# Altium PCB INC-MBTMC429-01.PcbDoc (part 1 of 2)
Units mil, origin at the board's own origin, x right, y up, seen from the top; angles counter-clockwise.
Board outline 6000 x 4000 mil, 2 copper layers (Top Layer, Bottom Layer); 198 components, 197 nets, 672 pads, 128 vias.
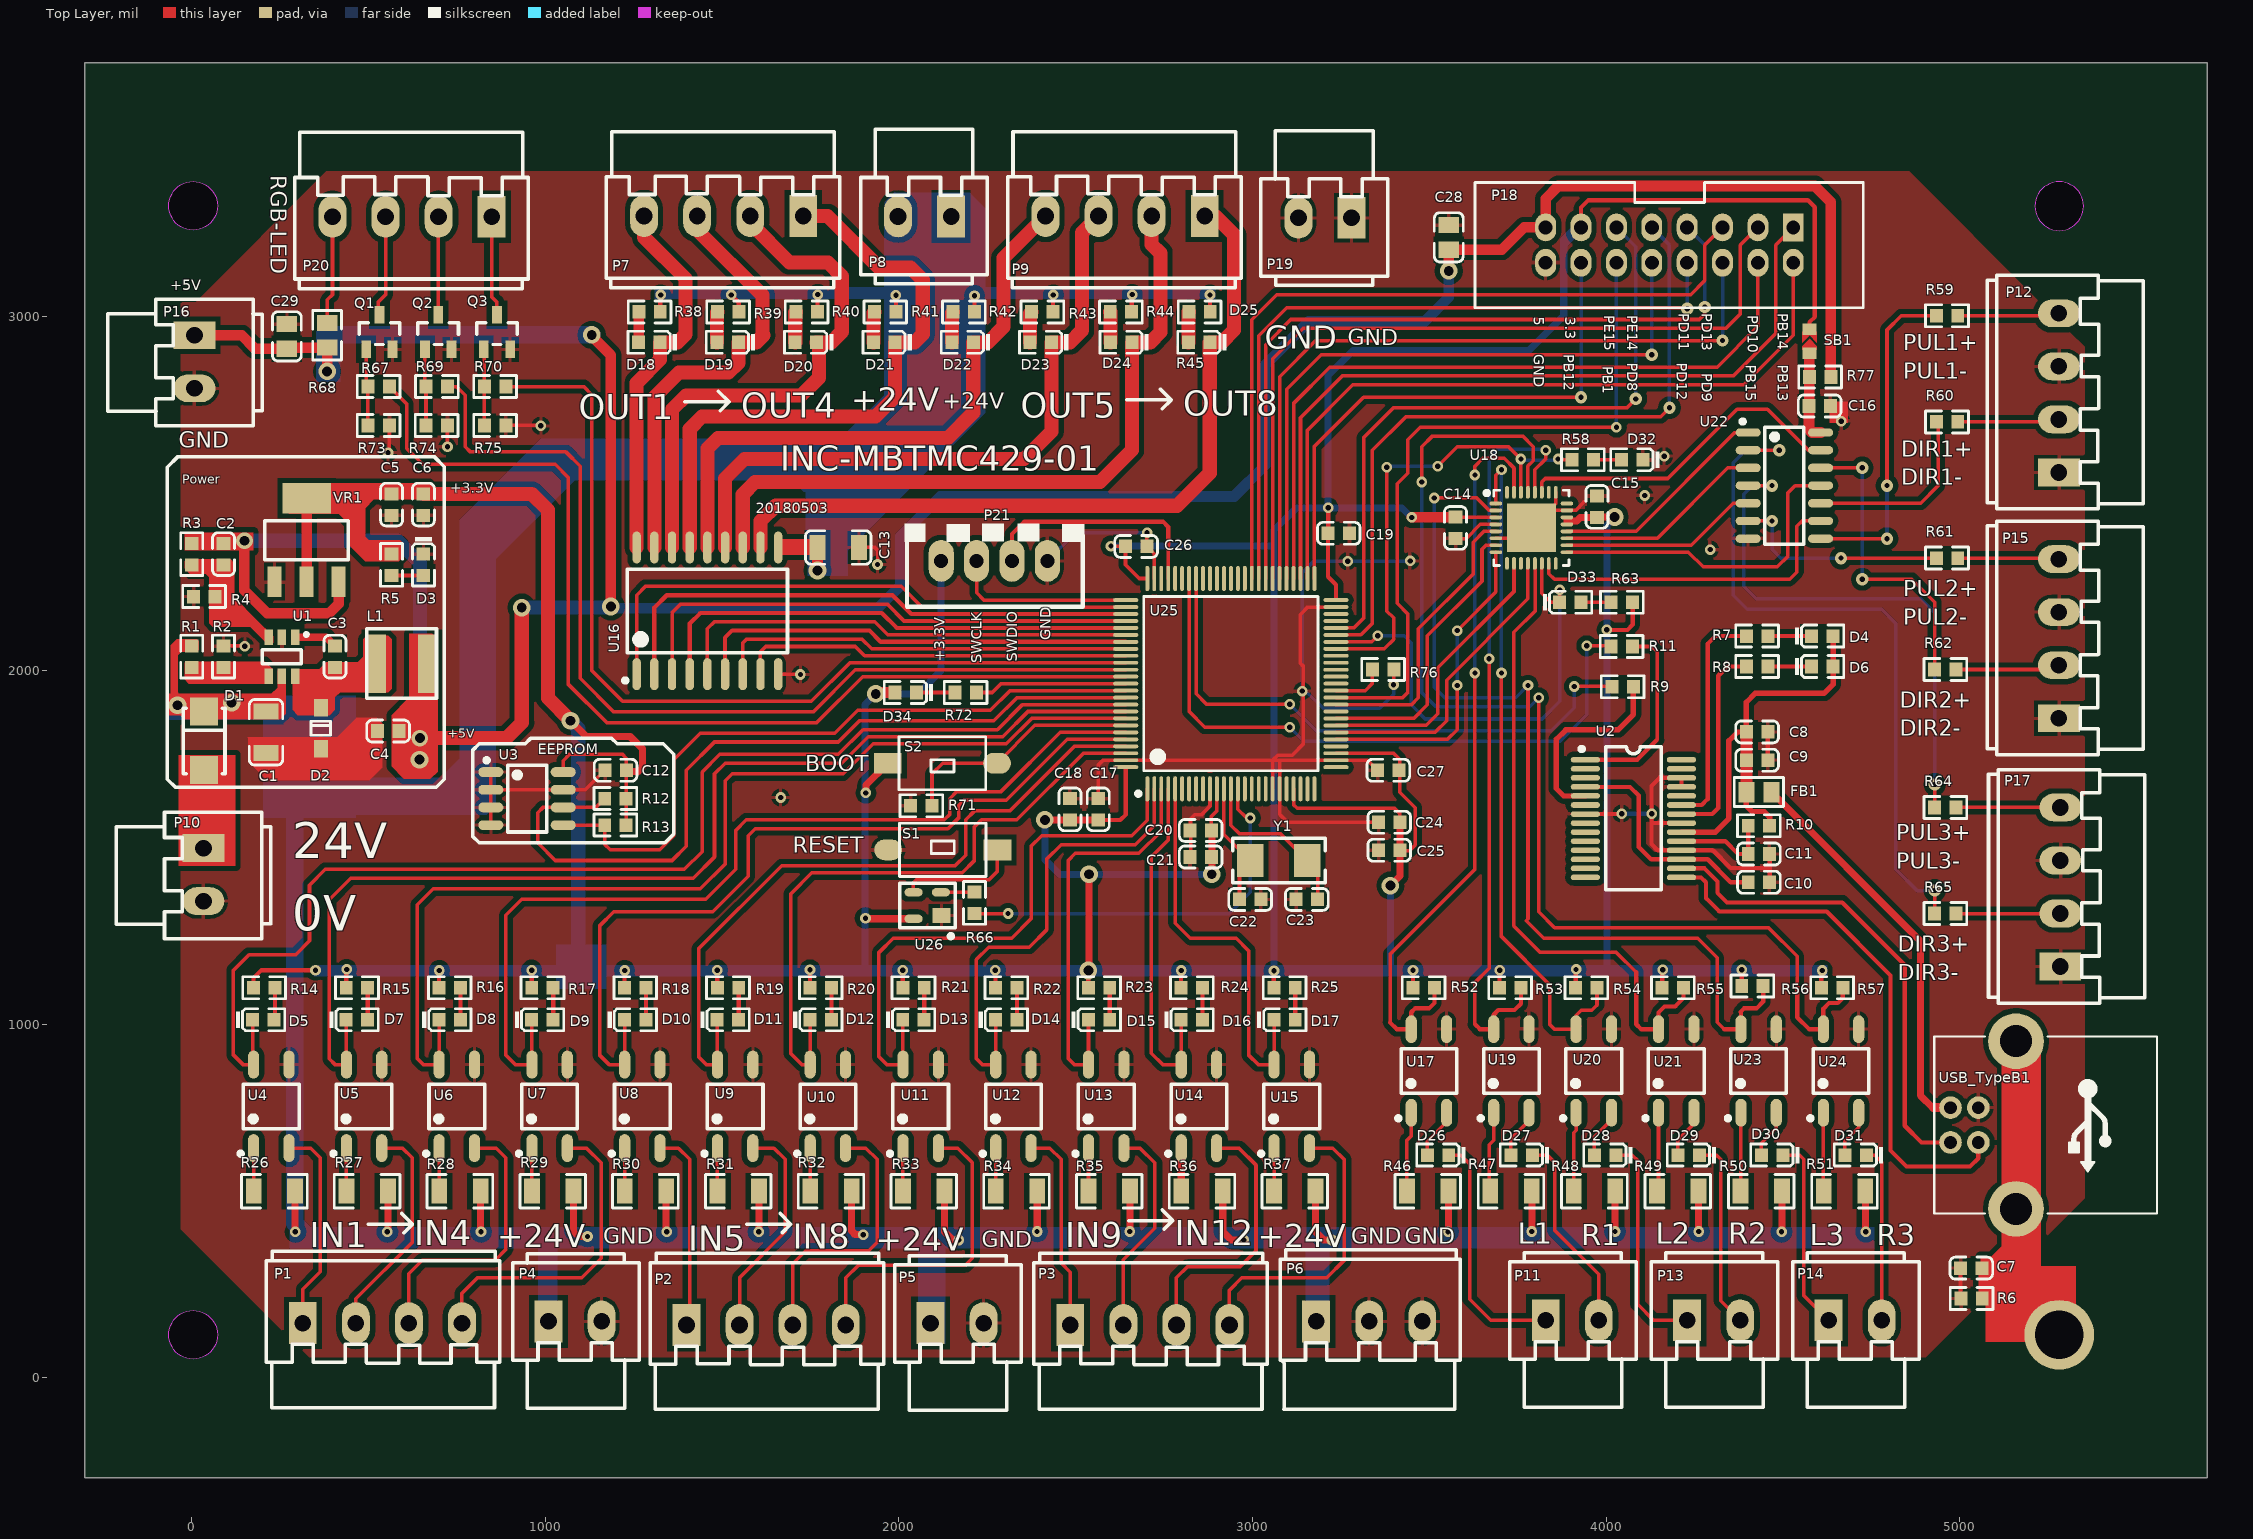
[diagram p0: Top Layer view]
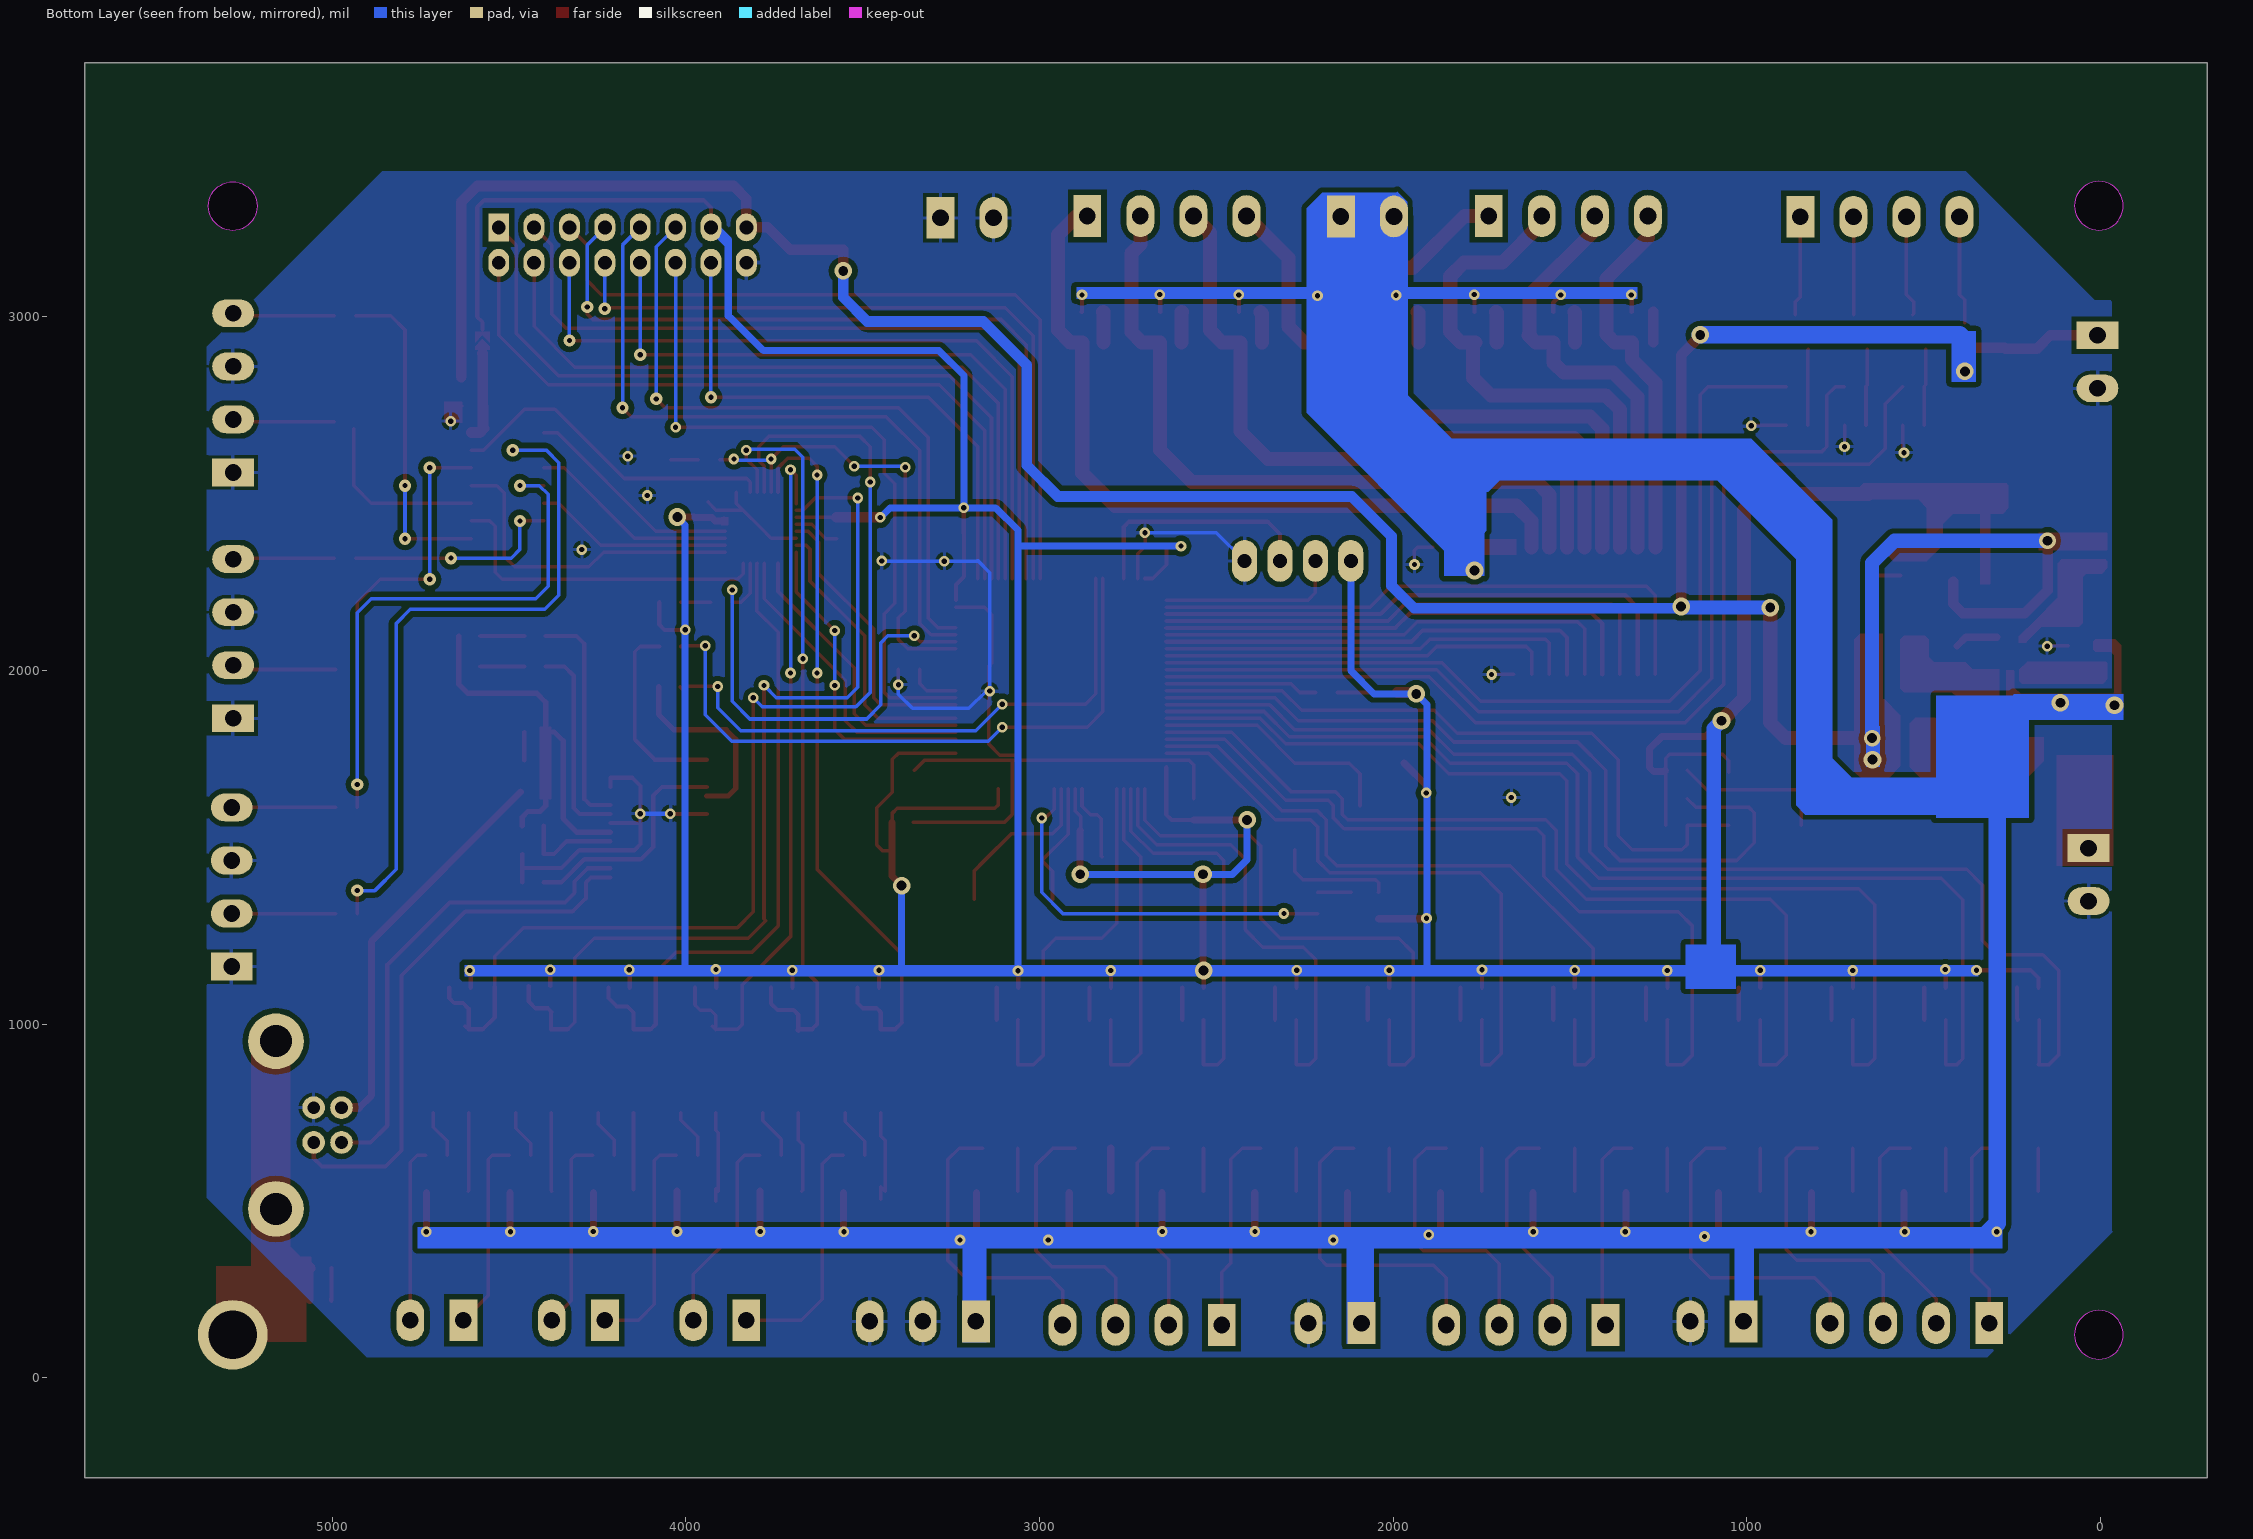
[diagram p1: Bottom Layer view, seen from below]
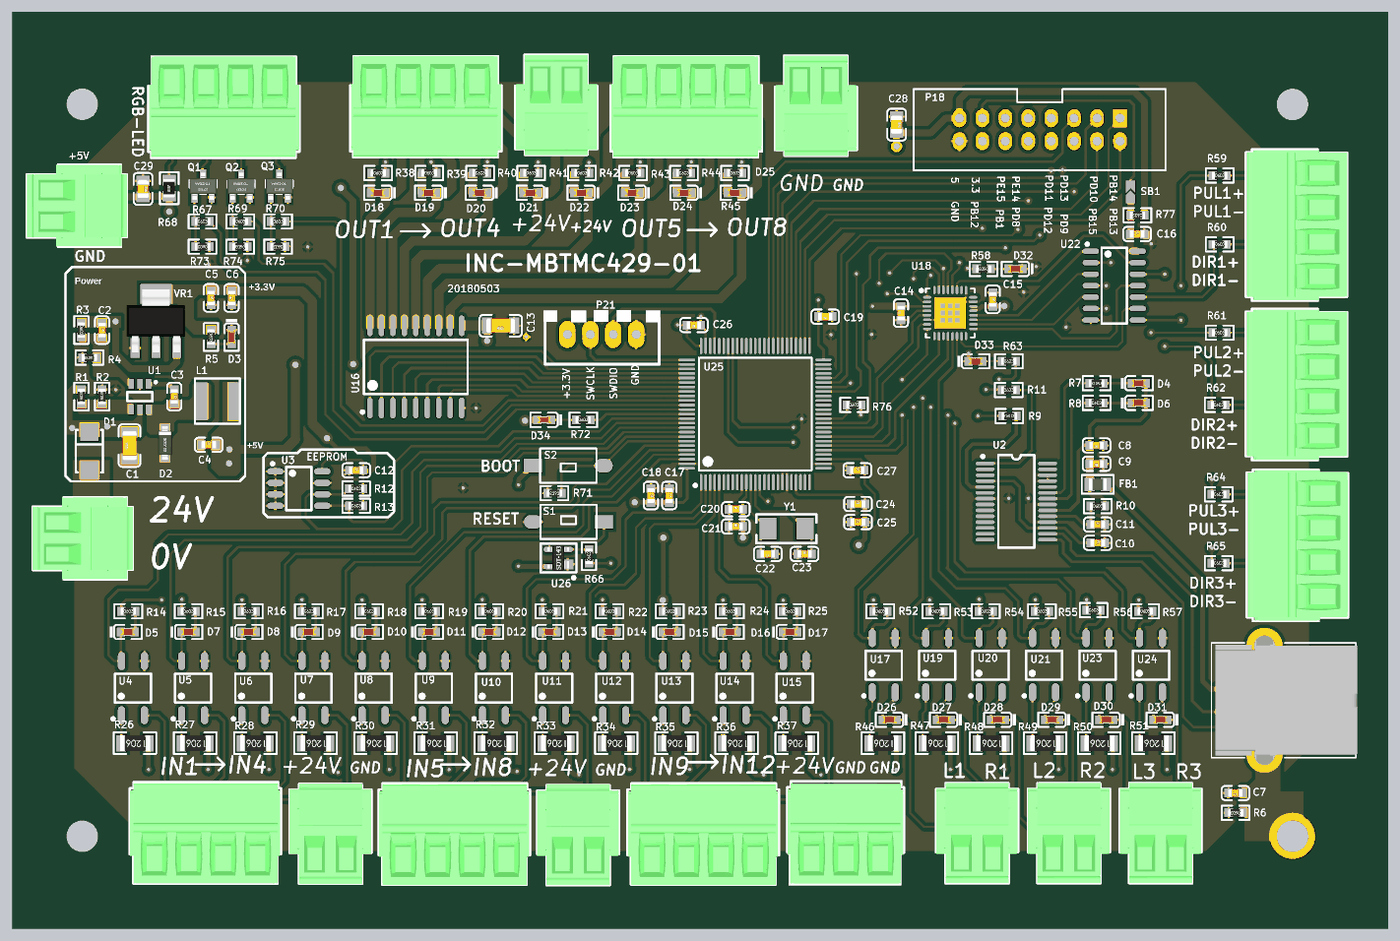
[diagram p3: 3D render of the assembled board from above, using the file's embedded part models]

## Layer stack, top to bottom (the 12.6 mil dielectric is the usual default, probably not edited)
Top Solder: solder mask 0.4, Solder Resist, Dk 3.5
Top Layer: signal copper 1.4
Dielectric 1: dielectric 12.6, FR-4, Dk 4.8
Bottom Layer: signal copper 1.4
Bottom Solder: solder mask 0.4, Solder Resist, Dk 3.5

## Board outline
-301,-282 5699,-282 5699,3718 -301,3718
cut-out: 5212.1,3313 ccw(c5281,3313) 5281,3244.1 ccw(c5281,3313) 5349.9,3313 ccw(c5281,3313) 5281,3381.9 ccw(c5281,3313)
cut-out: 5,3245.1 cw(c5,3314) -63.9,3314 cw(c5,3314) 5,3382.9 cw(c5,3314) 73.9,3314 cw(c5,3314)
cut-out: 5,53.1 cw(c5,122) -63.9,122 cw(c5,122) 5,190.9 cw(c5,122) 73.9,122 cw(c5,122)

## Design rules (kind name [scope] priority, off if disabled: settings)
Clearance [All] p1: gap=8 ignorepadtopadclearanceinfootprint=FALSE
MinimumSolderMaskSliver [All] p1 off: minsoldermaskwidth=10
PolygonConnect [All] p1: connectstyle=Relief reliefconductorwidth=10 reliefentries=4 polygonreliefangle="90 Angle" airgapwidth=10
RoutingVias [All] p1: holewidth=28 width=50 viastyle="Through Hole" minholewidth=15 minwidth=30 maxholewidth=28 maxwidth=50
SilkToSilkClearance [All] p1 off: silktosilkclearance=10
SilkToSolderMaskClearance [IsPad] p1 off: minsilkscreentomaskgap=10 clearancetoexposedcopper=TRUE
SolderMaskExpansion [All] p1: expansion=4
Width [All] p1: maxlimit=100 minlimit=10 preferedwidth=10
27 further rules are at their usual default settings.

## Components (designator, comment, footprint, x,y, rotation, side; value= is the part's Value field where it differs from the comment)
C1 "10uF (106) 10% 50V" 1206_C 211,1825.34 r90 top
C2 "33pF (330) 5% 50V" 0603_C 91,2329.32 r270 top
C3 "100nF (104) 10% 50V" 0603_C 406,2039.32 r270 top
C4 "10uF (106) 10% 10V" 0603_C 556.32,1829 r0 top
C5 "10uF (106) 10% 10V" 0603_C 566,2469.32 r270 top
C6 "100nF (104) 10% 50V" 0603_C 656,2469.32 r90 top
C7 "100nF (104) 10% 50V" 0603_C 5032.31,310.53 r180 top
C8 "10uF (106) 10% 10V" 0603_C 4426.69,1826.5 r180 top
C9 "100nF (104) 10% 50V" 0603_C 4426.69,1746.5 r180 top
C10 "100nF (104) 10% 50V" 0603_C 4432,1401.5 r0 top
C11 "100nF (104) 10% 50V" 0603_C 4432,1481.5 r0 top
C12 "100nF (104) 10% 50V" 0603_C 1199.32,1718 r0 top
C13 "10uF(106) ±10% 25V" 1206_C 1829,2348 r180 top
C14 "100nF (104) 10% 50V" 0603_C 3574,2403.32 r90 top
C15 "470nF (474) 10% 25V" 0603_C 3974,2463 r270 top
C16 "100nF (104) 10% 50V" 0603_C 4603.69,2748 r0 top
C17 "100nF (104) 10% 50V" 0603_C 2564,1607.68 r270 top
C18 "4.7uF (475) 10% 16V" 0603_C 2484,1607.68 r270 top
C19 "100nF (104) 10% 50V" 0603_C 3244,2388 r180 top
C20 "1uF (105) 10% 50V" 0603_C 2853.69,1548 r0 top
C21 "10nF (103) 10% 50V" 0603_C 2853.69,1473 r0 top
C22 "22pF (220) 5% 50V" 0603_C 2993.69,1353 r180 top
C23 "22pF (220) 5% 50V" 0603_C 3153.69,1353 r0 top
C24 "1uF (105) 10% 50V" 0603_C 3386.69,1571 r0 top
C25 "10nF (103) 10% 50V" 0603_C 3386.69,1492 r0 top
C26 "100nF (104) 10% 50V" 0603_C 2671.32,2351 r180 top
C27 "100nF (104) 10% 50V" 0603_C 3384,1718 r0 top
C28 "10uF (106) 10% 25V" 0805_C 3555,3224.96 r270 top
C29 "10uF (106) 10% 25V" 0805_C 270,2945.04 r270 top
D1 "SS210" SMA(DO-214AC)_S1 36,1801.32 r270 top
D2 "B5819W  SL" SOD-123 366,1837.07 r270 top
D3 "红灯 0603" 0603_LED_S1 656,2299.32 r270 top
D4 "蓝灯 0603" 0603_LED_S1 4611.31,2097.5 r0 top
D5 "蓝灯 0603" 0603_LED_S1 203.68,1013 r0 top
D6 "红灯 0603" 0603_LED_S1 4611.31,2011.5 r0 top
D7 "蓝灯 0603" 0603_LED_S1 467.96,1013 r0 top
D8 "蓝灯 0603" 0603_LED_S1 730.23,1013 r0 top
D9 "蓝灯 0603" 0603_LED_S1 992.5,1013 r0 top
D10 "蓝灯 0603" 0603_LED_S1 1254.78,1013 r0 top
D11 "蓝灯 0603" 0603_LED_S1 1517.05,1013 r0 top
D12 "蓝灯 0603" 0603_LED_S1 1779.32,1013 r0 top
D13 "蓝灯 0603" 0603_LED_S1 2041.59,1013 r0 top
D14 "蓝灯 0603" 0603_LED_S1 2303.87,1013 r0 top
D15 "蓝灯 0603" 0603_LED_S1 2566.14,1013 r0 top
D16 "蓝灯 0603" 0603_LED_S1 2828.41,1013 r0 top
D17 "蓝灯 0603" 0603_LED_S1 3090.68,1013 r0 top
D18 "蓝灯 0603" 0603_LED_S1 1294.69,2928 r180 top
D19 "蓝灯 0603" 0603_LED_S1 1516.11,2928 r180 top
D20 "蓝灯 0603" 0603_LED_S1 1737.54,2928 r180 top
D21 "蓝灯 0603" 0603_LED_S1 1958.97,2928 r180 top
D22 "蓝灯 0603" 0603_LED_S1 2180.4,2928 r180 top
D23 "蓝灯 0603" 0603_LED_S1 2401.83,2928 r180 top
D24 "蓝灯 0603" 0603_LED_S1 2629,2928 r180 top
D25 "蓝灯 0603" 0603_LED_S1 2849,2928 r180 top
D26 "红灯 0603" 0603_LED_S1 3524.69,630 r180 top
D27 "红灯 0603" 0603_LED_S1 3760.81,630 r180 top
D28 "红灯 0603" 0603_LED_S1 3996.94,630 r180 top
D29 "红灯 0603" 0603_LED_S1 4233.06,630 r180 top
D30 "红灯 0603" 0603_LED_S1 4469.19,630 r180 top
D31 "红灯 0603" 0603_LED_S1 4705.32,630 r180 top
D32 "蓝灯 0603" 0603_LED_S1 4073.32,2596 r180 top
D33 "红灯 0603" 0603_LED_S1 3899,2193 r0 top
D34 "蓝灯 0603" 0603_LED_S1 2019.32,1938 r180 top
FB1 "600Ω ±25% 100MHz" 0805_L 4432,1656.5 r0 top
L1 "3.3uH  ±20%" L5020 596,2019 r0 top value="4.7uH  ±10%"
P1 "Header 4" WJ15EDGVC-3.81-4P 315,155 r0 top
P2 "Header 4" WJ15EDGVC-3.81-4P 1400,150 r0 top
P3 "Header 4" WJ15EDGVC-3.81-4P 2485,150 r0 top
P4 "Header 2" WJ15EDGVC-3.81-2P 1010,160 r0 top
P5 "Header 2" WJ15EDGVC-3.81-2P 2090,155 r0 top
P6 "Header 3" WJ15EDGVC-3.81-3P 3180,160 r0 top
P7 "Header 4" WJ15EDGVC-3.81-4P 1730,3285 r180 top
P8 "Header 2" WJ15EDGVC-3.81-2P 2148,3284 r180 top
P9 "Header 4" WJ15EDGVC-3.81-4P 2865,3285 r180 top
P10 "Header 2" WJ15EDGVC-3.81-2P 34,1498 r270 top
P11 "Header 2" WJ15EDGVC-3.81-2P 3829,163 r0 top
P12 "Header 4" WJ15EDGVC-3.81-4P 5280,2560 r90 top
P13 "Header 2" WJ15EDGVC-3.81-2P 4229,163 r0 top
P14 "Header 2" WJ15EDGVC-3.81-2P 4629,163 r0 top
P15 "Header 4" WJ15EDGVC-3.81-4P 5280,1865 r90 top
P16 "Header 2" WJ15EDGVC-3.81-2P 9,2948 r270 top
P17 "Header 4" WJ15EDGVC-3.81-4P 5284,1163 r90 top
P18 "Header 8X2H" "直牛角连接器 2*8*2.54" 4529,3253 r180 top
P19 "Header 2" WJ15EDGVC-3.81-2P 3280,3280 r180 top
P20 "Header 4" WJ15EDGVC-3.81-4P 849,3283 r180 top
P21 "SWD" "XH连接器 4P-2.5" 2120,2310 r180 top
Q1 "SS8050 Y1" SOT-23(SOT-23-3) 531.6,2957.21 r270 top
Q2 "SS8050 Y1" SOT-23(SOT-23-3) 697.8,2957.21 r270 top
Q3 "SS8050 Y1" SOT-23(SOT-23-3) 864,2957.21 r270 top
R1 "47KΩ (4702) ±1%" 0603_R 1,2039.31 r90 top
R2 "10KΩ (1002) ±1%" 0603_R 91,2039.31 r90 top
R3 "160KΩ (1603) ±1%" 0603_R 1,2329.32 r270 top
R4 "30KΩ (3002) ±1%" 0603_R 36.32,2209 r180 top
R5 "1KΩ (1001) ±1%" 0603_R 566,2299 r270 top
R6 "47KΩ (4702) ±1%" 0603_R 5033,224.53 r180 top
R7 "1KΩ (1001) ±1%" 0603_R 4426.69,2097.5 r180 top
R8 "1KΩ (1001) ±1%" 0603_R 4426.68,2011.5 r0 top
R9 "33Ω (33R0) ±1%" 0603_R 4046.68,1954.5 r0 top
R10 "10KΩ (1002) ±1%" 0603_R 4432,1561.5 r0 top
R11 "33Ω (33R0) ±1%" 0603_R 4044,2068 r0 top
R12 "4.7KΩ (4701) ±1%" 0603_R 1199,1638 r0 top
R13 "4.7KΩ (4701) ±1%" 0603_R 1199,1563 r0 top
R14 "1KΩ (1001) ±1%" 0603_R 206,1103 r0 top
R15 "1KΩ (1001) ±1%" 0603_R 468.24,1103 r0 top
R16 "1KΩ (1001) ±1%" 0603_R 730.49,1103 r0 top
R17 "1KΩ (1001) ±1%" 0603_R 992.73,1103 r0 top
R18 "1KΩ (1001) ±1%" 0603_R 1254.98,1103 r0 top
R19 "1KΩ (1001) ±1%" 0603_R 1517.22,1103 r0 top
R20 "1KΩ (1001) ±1%" 0603_R 1779.46,1103 r0 top
R21 "1KΩ (1001) ±1%" 0603_R 2041.71,1103 r0 top
R22 "1KΩ (1001) ±1%" 0603_R 2303.95,1103 r0 top
R23 "1KΩ (1001) ±1%" 0603_R 2566.2,1103 r0 top
R24 "1KΩ (1001) ±1%" 0603_R 2828.44,1103 r0 top
R25 "1KΩ (1001) ±1%" 0603_R 3090.68,1103 r0 top
R26 "4.7KΩ (4701) ±1%" 1206_R 234.66,528 r180 top
R27 "4.7KΩ (4701) ±1%" 1206_R 496.93,528 r180 top
R28 "4.7KΩ (4701) ±1%" 1206_R 759.21,528 r180 top
R29 "4.7KΩ (4701) ±1%" 1206_R 1021.48,528 r180 top
R30 "4.7KΩ (4701) ±1%" 1206_R 1283.75,528 r180 top
R31 "4.7KΩ (4701) ±1%" 1206_R 1546.02,528 r180 top
R32 "4.7KΩ (4701) ±1%" 1206_R 1808.3,528 r180 top
R33 "4.7KΩ (4701) ±1%" 1206_R 2070.57,528 r180 top
R34 "4.7KΩ (4701) ±1%" 1206_R 2332.84,528 r180 top
R35 "4.7KΩ (4701) ±1%" 1206_R 2595.12,528 r180 top
R36 "4.7KΩ (4701) ±1%" 1206_R 2857.39,528 r180 top
R37 "4.7KΩ (4701) ±1%" 1206_R 3119.66,528 r180 top
R38 "6.8KΩ (6801) ±1%" 0603_R 1295.31,3014 r0 top
R39 "6.8KΩ (6801) ±1%" 0603_R 1517.46,3014 r0 top
R40 "6.8KΩ (6801) ±1%" 0603_R 1739.6,3014 r0 top
R41 "6.8KΩ (6801) ±1%" 0603_R 1961.74,3014 r0 top
R42 "6.8KΩ (6801) ±1%" 0603_R 2183.89,3014 r0 top
R43 "6.8KΩ (6801) ±1%" 0603_R 2406.03,3014 r0 top
R44 "6.8KΩ (6801) ±1%" 0603_R 2628.17,3014 r0 top
R45 "6.8KΩ (6801) ±1%" 0603_R 2850.31,3014 r0 top
R46 "4.7KΩ (4701) ±1%" 1206_R 3495.38,528 r180 top
R47 "4.7KΩ (4701) ±1%" 1206_R 3731.11,528 r180 top
R48 "4.7KΩ (4701) ±1%" 1206_R 3966.83,528 r180 top
R49 "4.7KΩ (4701) ±1%" 1206_R 4202.55,528 r180 top
R50 "4.7KΩ (4701) ±1%" 1206_R 4438.28,528 r180 top
R51 "4.7KΩ (4701) ±1%" 1206_R 4674,528 r180 top
R52 "1KΩ (1001) ±1%" 0603_R 3484,1103 r0 top
R53 "1KΩ (1001) ±1%" 0603_R 3728.68,1103 r0 top
R54 "1KΩ (1001) ±1%" 0603_R 3944,1103 r0 top
R55 "1KΩ (1001) ±1%" 0603_R 4188.68,1103 r0 top
R56 "1KΩ (1001) ±1%" 0603_R 4413.68,1108 r0 top
R57 "1KΩ (1001) ±1%" 0603_R 4638.68,1103 r0 top
R58 "1KΩ (1001) ±1%" 0603_R 3934.32,2596 r180 top
R59 "220Ω (2200) ±1%" 0603_R 4963.68,3003 r0 top
R60 "220Ω (2200) ±1%" 0603_R 4963.68,2703 r0 top
R61 "220Ω (2200) ±1%" 0603_R 4963.68,2318 r0 top
R62 "220Ω (2200) ±1%" 0603_R 4959,2003 r0 top
R63 "1KΩ (1001) ±1%" 0603_R 4044.31,2193 r0 top
R64 "220Ω (2200) ±1%" 0603_R 4959,1613 r0 top
R65 "220Ω (2200) ±1%" 0603_R 4959,1313 r0 top
R66 "4.7KΩ (4701) ±1%" 0603_R 2214,1343 r90 top
R67 "2.2KΩ (2201) ±1%" 0603_R 529.31,2803 r0 top
R68 "1KΩ (1001) ±1%" 0805_R 384,2948.04 r90 top
R69 "2.2KΩ (2201) ±1%" 0603_R 694.16,2803 r0 top
R70 "2.2KΩ (2201) ±1%" 0603_R 859,2803 r0 top
R71 "100KΩ (1003) ±1%" 0603_R 2063.69,1618 r180 top
R72 "510Ω (5100) ±1%" 0603_R 2189,1938 r0 top
R73 "100KΩ (1003) ±1%" 0603_R 529.32,2693 r180 top
R74 "100KΩ (1003) ±1%" 0603_R 693.69,2693 r180 top
R75 "100KΩ (1003) ±1%" 0603_R 858.69,2693 r180 top
R76 "100KΩ (1003) ±1%" 0603_R 3369.31,2003 r0 top
R77 "0Ω (0R0) ±1%" 0603_R 4605,2830 r180 top
S1 "贴片按键 3*6*2.5" "贴片按键 3*6*2.5" 2279,1493 r180 top
S2 "贴片按键 3*6*2.5" "贴片按键 3*6*2.5" 1969,1738 r0 top
SB1 "Circuit Breaker" JP2_SMD 4575,2897.5 r90 top
U1 "MP2451DT-LF-Z" SOT-23-6 256,2039 r90 top
U2 "FT232RL-REEL" SSOP-28_208mil 4077,1581.5 r270 top
U3 "EEPROM/AT24C128" SOIC-8_150mil 949,1638 r270 top
U4 "EL357N(B)(TA)-G" SOP-4_P2.54 226,768 r90 top
U5 "EL357N(B)(TA)-G" SOP-4_P2.54 488.27,768 r90 top
U6 "EL357N(B)(TA)-G" SOP-4_P2.54 750.55,768 r90 top
U7 "EL357N(B)(TA)-G" SOP-4_P2.54 1012.82,768 r90 top
U8 "EL357N(B)(TA)-G" SOP-4_P2.54 1275.09,768 r90 top
U9 "EL357N(B)(TA)-G" SOP-4_P2.54 1537.36,768 r90 top
U10 "EL357N(B)(TA)-G" SOP-4_P2.54 1799.64,768 r90 top
U11 "EL357N(B)(TA)-G" SOP-4_P2.54 2061.91,768 r90 top
U12 "EL357N(B)(TA)-G" SOP-4_P2.54 2324.18,768 r90 top
U13 "EL357N(B)(TA)-G" SOP-4_P2.54 2586.45,768 r90 top
U14 "EL357N(B)(TA)-G" SOP-4_P2.54 2848.73,768 r90 top
U15 "EL357N(B)(TA)-G" SOP-4_P2.54 3111,768 r90 top
U16 "ULN2803ADW" SOIC-18_300mil 1459,2168.87 r0 top
U17 "EL357N(B)(TA)-G" SOP-4_P2.54 3499,868 r90 top
U18 "TMC429-LI" QFN-32_5x5x05P 3788.61,2403.47 r270 top
U19 "EL357N(B)(TA)-G" SOP-4_P2.54 3732,868 r90 top
U20 "EL357N(B)(TA)-G" SOP-4_P2.54 3965,868 r90 top
U21 "EL357N(B)(TA)-G" SOP-4_P2.54 4198,868 r90 top
U22 "74HC04D" SOIC-14_150mil 4504,2523 r270 top
U23 "EL357N(B)(TA)-G" SOP-4_P2.54 4431,868 r90 top
U24 "EL357N(B)(TA)-G" SOP-4_P2.54 4664,868 r90 top
U25 "STM32F103VET6" LQFP-100_14x14x05P 2939,1963 r0 top
U26 "IMP811" SOT-143 2081.2,1335.6 r0 top
USB_TypeB1 "USB-B" USB_TypeB 5012.72,715.01 r270 top
VR1 "AMS1117-3.3" SOT-223 326,2369 r270 top
Y1 "8MHz ±20ppm 20pF" SMD-5032_2P 3074.71,1463 r180 top

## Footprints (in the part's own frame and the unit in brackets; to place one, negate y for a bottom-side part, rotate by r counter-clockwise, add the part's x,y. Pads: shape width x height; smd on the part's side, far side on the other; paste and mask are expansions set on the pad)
0603_C [mm]
  rect 0.93x0.98 smd: 1(-0.77,0) 2(0.77,0)
  silkscreen extent -1.53,-0.79 1.54,0.79, body extent -0.8,-0.4 0.8,0.4, height 0.3
0603_LED_S1 [mm]
  rect 0.93x0.98 smd: A(0.77,0) K(-0.77,0)
  silkscreen extent -1.98,-0.79 1.54,0.79, body extent -0.8,-0.4 0.8,0.4, height 0.6
0603_R [mm]
  rect 0.93x0.98 smd: 1(-0.77,0) 2(0.77,0)
  silkscreen extent -1.53,-0.79 1.54,0.79, body extent -0.85,-0.4 0.85,0.4, height 0.56
0805_C [mm]
  rect 1.16x1.47 smd: 1(-0.89,0) 2(0.89,0)
  silkscreen extent -1.77,-1.04 1.77,1.04, body extent -1,-0.62 1,0.63, height 0.77
0805_L [mm]
  rect 1.16x1.47 smd: 1(-0.89,0) 2(0.89,0)
  silkscreen extent -1.77,-1.04 1.77,1.03, body extent -1.02,-0.64 1.03,0.64, height 0.6
0805_R [mm]
  rect 1.16x1.47 smd: 1(-0.89,0) 2(0.89,0)
  silkscreen extent -1.77,-1.04 1.77,1.03, body extent -1,-0.62 1,0.63, height 0.49
1206_C [mm]
  rect 1.13x1.8 smd: 1(-1.49,0) 2(1.49,0)
  silkscreen extent -2.36,-1.2 2.35,1.2, body extent -1.6,-0.81 1.6,0.79, height 1
1206_R [mm]
  rect 1.13x1.8 smd: 1(-1.49,0) 2(1.49,0)
  silkscreen extent -2.36,-1.2 2.35,1.2, body extent -1.7,-0.86 1.65,0.87, height 0.85
JP2_SMD [mil] "短路焊点"
  rect 32x40 smd: 1(0,0) 2(67.5,0)
  Top Layer region: 60,0 50,0 30,20 60,20
  Top Layer region: 60,0 50,0 30,-20 60,-20
  Top Layer region: 10,-20 20,-20 40,0 20,20 10,20
L5020 [mm] "XCP 功率电感 5*5*2"
  rect 1.4x4.2 smd: 1(-1.85,0) 2(1.85,0)
  silkscreen extent -2.54,-2.49 2.46,2.51
LQFP-100_14x14x05P [mm]
  oval 0.28x1.8 smd mask+0.051: 1(-6,-7.55) 2(-5.5,-7.55) 3(-5,-7.55) 4(-4.5,-7.55) 5(-4,-7.55) 6(-3.5,-7.55) 7(-3,-7.55) 8(-2.5,-7.55) 9(-2,-7.55) 10(-1.5,-7.55) 11(-1,-7.55) 12(-0.5,-7.55) 13(0,-7.55) 14(0.5,-7.55) 15(1,-7.55) 16(1.5,-7.55) 17(2,-7.55) 18(2.5,-7.55) 19(3,-7.55) 20(3.5,-7.55) 21(4,-7.55) 22(4.5,-7.55) 23(5,-7.55) 24(5.5,-7.55) 25(6,-7.55) 51(6,7.55) 52(5.5,7.55) 53(5,7.55) 54(4.5,7.55) 55(4,7.55) 56(3.5,7.55) 57(3,7.55) 58(2.5,7.55) 59(2,7.55) 60(1.5,7.55) 61(1,7.55) 62(0.5,7.55) 63(0,7.55) 64(-0.5,7.55) 65(-1,7.55) 66(-1.5,7.55) 67(-2,7.55) 68(-2.5,7.55) 69(-3,7.55) 70(-3.5,7.55) 71(-4,7.55) 72(-4.5,7.55) 73(-5,7.55) 74(-5.5,7.55) 75(-6,7.55)
  oval 1.8x0.28 smd mask+0.051: 26(7.55,-6) 27(7.55,-5.5) 28(7.55,-5) 29(7.55,-4.5) 30(7.55,-4) 31(7.55,-3.5) 32(7.55,-3) 33(7.55,-2.5) 34(7.55,-2) 35(7.55,-1.5) 36(7.55,-1) 37(7.55,-0.5) 38(7.55,0) 39(7.55,0.5) 40(7.55,1) 41(7.55,1.5) 42(7.55,2) 43(7.55,2.5) 44(7.55,3) 45(7.55,3.5) 46(7.55,4) 47(7.55,4.5) 48(7.55,5) 49(7.55,5.5) 50(7.55,6) 76(-7.55,6) 77(-7.55,5.5) 78(-7.55,5) 79(-7.55,4.5) 80(-7.55,4) 81(-7.55,3.5) 82(-7.55,3) 83(-7.55,2.5) 84(-7.55,2) 85(-7.55,1.5) 86(-7.55,1) 87(-7.55,0.5) 88(-7.55,0) 89(-7.55,-0.5) 90(-7.55,-1) 91(-7.55,-1.5) 92(-7.55,-2) 93(-7.55,-2.5) 94(-7.55,-3) 95(-7.55,-3.5) 96(-7.55,-4) 97(-7.55,-4.5) 98(-7.55,-5) 99(-7.55,-5.5) 100(-7.55,-6)
  silkscreen extent -6.8,-8.05 6.25,6.25
QFN-32_5x5x05P [mm]
  rect 3.5x3.5 smd paste-1.75 mask+0.051: 0(0,0)
  oval 0.28x0.9 smd mask+0.051: 1(-1.75,-2.55) 2(-1.25,-2.55) 3(-0.75,-2.55) 4(-0.25,-2.55) 5(0.25,-2.55) 6(0.75,-2.55) 7(1.25,-2.55) 8(1.75,-2.55) 17(1.75,2.55) 18(1.25,2.55) 19(0.75,2.55) 20(0.25,2.55) 21(-0.25,2.55) 22(-0.75,2.55) 23(-1.25,2.55) 24(-1.75,2.55)
  oval 0.9x0.28 smd mask+0.051: 9(2.55,-1.75) 10(2.55,-1.25) 11(2.55,-0.75) 12(2.55,-0.25) 13(2.55,0.25) 14(2.55,0.75) 15(2.55,1.25) 16(2.55,1.75) 25(-2.55,1.75) 26(-2.55,1.25) 27(-2.55,0.75) 28(-2.55,0.25) 29(-2.55,-0.25) 30(-2.55,-0.75) 31(-2.55,-1.25) 32(-2.55,-1.75)
  silkscreen extent -2.7,-3.35 2.7,2.7
SMA(DO-214AC)_S1 [mm]
  rect 2x2 smd: 1(2.1,0) 2(-2.1,0)
  silkscreen extent -2.35,-1.5 2.35,1.5
SMD-5032_2P [mm]
  rect 1.9x2.4 smd: 1(-2.05,0) 2(2.05,0)
  silkscreen extent -3.32,-1.6 3.32,1.6
SOD-123 [mm]
  rect 1.25x1 smd: 1(1.475,0) 2(-1.475,0)
  silkscreen extent -0.5,-0.7 0.5,0.7, body extent -1.85,-0.77 1.85,0.78, height 1.35
SOIC-8_150mil [mm]
  oval 0.7x1.8 smd: 1(-1.905,-2.6) 2(-0.635,-2.6) 3(0.635,-2.6) 4(1.905,-2.6) 5(1.905,2.6) 6(0.635,2.6) 7(-0.635,2.6) 8(-1.905,2.6)
  silkscreen extent -2.9,-3.05 2.4,1.4
SOIC-14_150mil [mm]
  oval 0.6x1.8 smd: 1(-3.81,-2.6) 2(-2.54,-2.6) 3(-1.27,-2.6) 4(0,-2.6) 5(1.27,-2.6) 6(2.54,-2.6) 7(3.81,-2.6) 8(3.81,2.6) 9(2.54,2.6) 10(1.27,2.6) 11(0,2.6) 12(-1.27,2.6) 13(-2.54,2.6) 14(-3.81,2.6)
  silkscreen extent -4.75,-3.15 4.2,1.4
SOIC-18_300mil [mm]
  oval 0.6x2.3 smd: 1(-5.08,-4.55) 2(-3.81,-4.55) 3(-2.54,-4.55) 4(-1.27,-4.55) 5(0,-4.55) 6(1.27,-4.55) 7(2.54,-4.55) 8(3.81,-4.55) 9(5.08,-4.55) 10(5.08,4.55) 11(3.81,4.55) 12(2.54,4.55) 13(1.27,4.55) 14(0,4.55) 15(-1.27,4.55) 16(-2.54,4.55) 17(-3.81,4.55) 18(-5.08,4.55)
  silkscreen extent -6.05,-5.15 5.75,3
SOP-4_P2.54 [mm]
  oval 2x0.8 smd: 1(-3,1.27) 2(-3,-1.27) 3(3,-1.27) 4(3,1.27)
  silkscreen extent -3.55,-2 1.6,2.35
SOT-23(SOT-23-3) [mm]
  rect 1.25x0.7 smd: 1(1.25,-0.95) 2(1.25,0.95) 3(-1.25,0)
  silkscreen extent -0.65,-1.46 0.9,1.46, body extent -1.5,-1.5 1.5,1.5, height 1.3
SOT-23-6 [mm]
  rect 1.1x0.6 smd: 1(1.4,-0.95) 2(1.4,0) 3(1.4,0.95) 4(-1.4,0.95) 5(-1.4,0) 6(-1.4,-0.95)
  silkscreen extent -0.5,-1.87 1.72,1.4
SOT-143 [mm]
  rect 1.3x1.1 smd: 1(1,-0.71)
  oval 1.3x0.6 smd: 2(0.96,0.95) 3(-1,0.95) 4(-1,-0.95)
  silkscreen extent -1.98,-2.35 1.98,1.6, body extent -1.23,-1.46 1.19,1.46, height 1
SOT-223 [mm]
  rect 2.2x1 smd: 1(3,-2.3) 2(3,0) 3(3,2.3)
  rect 2.2x3.5 smd: 2(-3,0)
  silkscreen extent -1.4,-3 1.4,3, body extent -3.49,-3.24 3.49,3.24, height 1.64
SSOP-28_208mil [mm]
  oval 0.4x2.1 smd mask+0.051: 1(-4.225,-3.45) 2(-3.575,-3.45) 3(-2.925,-3.45) 4(-2.275,-3.45) 5(-1.625,-3.45) 6(-0.975,-3.45) 7(-0.325,-3.45) 8(0.325,-3.45) 9(0.975,-3.45) 10(1.625,-3.45) 11(2.275,-3.45) 12(2.925,-3.45) 13(3.575,-3.45) 14(4.225,-3.45) 15(4.225,3.45) 16(3.575,3.45) 17(2.925,3.45) 18(2.275,3.45) 19(1.625,3.45) 20(0.975,3.45) 21(0.325,3.45) 22(-0.325,3.45) 23(-0.975,3.45) 24(-1.625,3.45) 25(-2.275,3.45) 26(-2.925,3.45) 27(-3.575,3.45) 28(-4.225,3.45)
  silkscreen extent -5.15,-3.86 5.1,2
USB_TypeB [mil]
  round 64 hole 36 mask+1: 1(-49.21,-39.16) 2(49.21,-39.16) 3(49.21,39.58) 4(-49.21,39.58)
  round 157.48 hole 90.55 mask+0: 5(-237.01,146.28) 6(237.01,146.28)
  silkscreen extent -250,-85 250,545, body extent -283,-67 283,551, height 453
WJ15EDGVC-3.81-2P [mm] "XCP 15EDG连接器 直 插件 P=3.81"
  rect 2x3 hole 1.2: 1(0,0)
  oval 2x3 hole 1.2: 2(3.81,0)
  silkscreen extent -2.59,-6.25 6.5,4.85, body extent -2.57,-6.22 6.44,4.88, height 18.95
WJ15EDGVC-3.81-3P [mm] "XCP 15EDG连接器 直 插件 P=3.81"
  rect 2x3 hole 1.2: 1(0,0)
  oval 2x3 hole 1.2: 2(3.81,0) 3(7.62,0)
  silkscreen extent -2.59,-6.3 10.34,5.13, body extent -2.56,-6.2 10.26,4.9, height 18.6
WJ15EDGVC-3.81-4P [mm] "XCP 15EDG连接器 直 插件 P=3.81"
  rect 2x3 hole 1.2: 1(0,0)
  oval 2x3 hole 1.2: 2(3.81,0) 3(7.62,0) 4(11.43,0)
  silkscreen extent -2.62,-6.07 14.15,5.16, body extent -2.57,-6.07 14.06,5.03, height 18.6
"XH连接器 4P-2.5" [mil] "XCP"
  oval 71x118 hole 39.37: 1(0,0) 2(-100,0) 3(-200,0) 4(-300,0)
  silkscreen extent -405,-106 103,130
"直牛角连接器 2*8*2.54" [mm] "XCP"
  rect 1.5x2 hole 1: 1(0,0)
  oval 1.5x2 hole 1: 2(0,2.54) 3(2.54,0) 4(2.54,2.54) 5(5.08,0) 6(5.08,2.54) 7(7.62,0) 8(7.62,2.54) 9(10.16,0) 10(10.16,2.54) 11(12.7,0) 12(12.7,2.54) 13(15.24,0) 14(15.24,2.54) 15(17.78,0) 16(17.78,2.54)
  silkscreen extent -5.03,-3.23 22.86,5.77
"贴片按键 3*6*2.5" [mm] "XCP"
  rect 2x1.5 smd: 1(0,0)
  oval 2x1.5 smd: 2(7.849,0)
  silkscreen extent 0.81,-1.91 7.04,1.91

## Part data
C1: library part "1206 10uF (106) 10% 50V", "贴片电容", Package=1206, SuppliersPartNumber=C13585
C2: library part "0603 33pF (330) 5% 50V", "贴片电容", Package=0603, SuppliersPartNumber=C1663
C3 C6 C7 C9 C10 C11 C12 C14 C16 C17 C19 C26 C27: library part "0603 100nF (104) 10% 50V", "贴片电容", Package=0603, SuppliersPartNumber=C14663
C4 C5 C8: library part "0603 10uF (106) 10% 10V", "贴片电容", Package=0603, SuppliersPartNumber=C19702
C13: library part Cap, "Capacitor"
C15: library part "0603 470nF (474) 10% 25V", "贴片电容", Package=0603, SuppliersPartNumber=C1623
C18: library part "0603 4.7uF (475) 10% 16V", "贴片电容", Package=0603, SuppliersPartNumber=C19666
C20 C24: library part "0603 1uF (105) 10% 50V", "贴片电容", Package=0603, SuppliersPartNumber=C15849
C21 C25: library part "0603 10nF (103) 10% 50V", "贴片电容", Package=0603, SuppliersPartNumber=C57112
C22 C23: library part "0603 22pF (220) 5% 50V", "贴片电容", Package=0603, SuppliersPartNumber=C1653
C28 C29: library part "0805 10uF (106) 10% 25V", "贴片电容", Package=0805, SuppliersPartNumber=C15850
D1: library part "SMA(DO-214AC) SS210", "二极管", Package=SMA(DO-214AC), SuppliersPartNumber=C14996
D2: library part "SOD-123 B5819W  SL", "肖特基二极管", Package=SOD-123, SuppliersPartNumber=C8598
D3 D6 D26 D27 D28 D29 D30 D31 D33: library part "0603 红灯", "发光二极管", Package=0603, SuppliersPartNumber=C2286
D4 D5 D7 D8 D9 D10 D11 D12 D13 D14 D15 D16 D17 D18 D19 D20 D21 D22 D23 D24 D25 D32 D34: library part "0603 蓝灯", "发光二极管", Package=0603, SuppliersPartNumber=C72041
FB1: library part "0805 600Ω 25% 100MHz", "贴片磁珠", Package=0805, SuppliersPartNumber=C1017
L1: library part Inductor, "Inductor"
P1 P2 P3 P7 P9 P12 P15 P17 P20: "Header, 4-Pin"
P4 P5 P8 P10 P11 P13 P14 P16 P19: "Header, 2-Pin"
P6: "Header, 3-Pin"
P18: "Header, 8-Pin, Dual row, Right Angle"
P21: library part MHDR1X4, "Header, 4-Pin"
Q1 Q2 Q3: library part "SOT-23 SS8050 Y1", "三极管", Package=SOT-23, SuppliersPartNumber=C2150
R1 R6: library part "0603 47KΩ (4702) 1%", "贴片电阻", Package=0603, SuppliersPartNumber=C25819
R2 R10 R12 R13: library part "0603 10KΩ (1002) 1%", "贴片电阻", Package=0603, SuppliersPartNumber=C25804
R3: library part "0603 130KΩ (1303) 1%", "贴片电阻", Package=0603, SuppliersPartNumber=C22795
R4: library part "0603 24KΩ (2402) 1%", "贴片电阻", Package=0603, SuppliersPartNumber=C23352
R5 R7 R8 R14 R15 R16 R17 R18 R19 R20 R21 R22 R23 R24 R25 R52 R53 R54 R55 R56 R57 R58 R63: library part "0603 1KΩ (1001) 1%", "贴片电阻", Package=0603, SuppliersPartNumber=C21190
R9 R11: library part "0603 330Ω (3300) 1%", "贴片电阻", Package=0603, SuppliersPartNumber=C23138
R26 R27 R28 R29 R30 R31 R32 R33 R34 R35 R36 R37 R46 R47 R48 R49 R50 R51: library part "1206 4.7KΩ (4701) 1%", "贴片电阻", Package=1206, SuppliersPartNumber=C17936
R38 R39 R40 R41 R42 R43 R44 R45: library part "0603 6.8KΩ (6801) 1%", "贴片电阻", Package=0603, SuppliersPartNumber=C23212
R59 R60 R61 R62 R64 R65: library part "0603 220Ω (2200) 1%", "贴片电阻", Package=0603, SuppliersPartNumber=C22962
R66: library part "0603 4.7KΩ (4701) 1%", "贴片电阻", Package=0603, SuppliersPartNumber=C23162
R67 R69 R70: library part "0603 2.2KΩ (2201) 1%", "贴片电阻", Package=0603, SuppliersPartNumber=C4190
R68: library part "0805 2KΩ (2001) 1%", "贴片电阻", Package=0805, SuppliersPartNumber=C17604
R71 R73 R74 R75 R76: library part "0603 100KΩ (1003) 1%", "贴片电阻", Package=0603, SuppliersPartNumber=C25803
R72: library part "0603 510Ω (5100) 1%", "贴片电阻", Package=0603, SuppliersPartNumber=C23193
R77: library part "0603 0Ω (0R0) 1%", "贴片电阻", Package=0603, SuppliersPartNumber=C21189
S1 S2: library part SW-PB, "Switch"
U1: "DC-DCоƬ", Package=SOT-23-6, SuppliersPartNumber=C14123
U2: library part FT232RL
U3: library part EEPROM/AT24C256C-SSHL-T_[C6482], "EEPROM", Package=SOIC-8_150mil, SuppliersPartNumber=C6482
U4 U5 U6 U7 U8 U9 U10 U11 U12 U13 U14 U15 U17 U19 U20 U21 U23 U24: "贴片光耦", Package=SOP-4_P2.54, SuppliersPartNumber=C6649
U16: "大电流驱动", Package=SOIC-18_300mil, SuppliersPartNumber=C9683
U22: library part 74HC04
USB_TypeB1: library part USB-6
VR1: library part "SOT-223 AMS1117-3.3", "低压差线性稳压(LDO)", Package=SOT-223, SuppliersPartNumber=C6186
Y1: library part "SMD-5032_2P 8MHz 20ppm 20pF", "贴片晶振", Package=SMD-5032_2P, SuppliersPartNumber=C115962

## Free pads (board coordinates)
  round 196.85 hole 137.8: 0(5281,122)

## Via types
v1: diameter 30, hole 15, Top Layer to Bottom Layer, tented both sides, 91 vias
v2: diameter 35, hole 15, Top Layer to Bottom Layer, tented both sides, 17 vias
v3: diameter 50, hole 28, Top Layer to Bottom Layer, tented both sides, 16 vias
v4: diameter 47.24, hole 28, Top Layer to Bottom Layer, tented both sides, 2 vias
v5: diameter 30, hole 15, Top Layer to Bottom Layer, 1 vias
v6: diameter 50, hole 28, Top Layer to Bottom Layer, 1 vias

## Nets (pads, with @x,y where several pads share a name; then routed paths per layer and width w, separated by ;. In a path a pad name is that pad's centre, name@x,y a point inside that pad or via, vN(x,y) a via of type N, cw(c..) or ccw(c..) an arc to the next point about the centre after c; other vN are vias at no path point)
+3.3V: C5.1 C6.2 C12.2 C14.2 C15.2 C17.2 C18.2 C19.2 C20.2 C21.2 C24.2 C25.2 C26.2 C27.2 D34.A P18.13 P21.1 R5.1 R12.2 R13.2 R14.1 R15.1 R16.1 R17.1 R18.1 R19.1 R20.1 R21.1 R22.1 R23.1 R24.1 R25.1 R52.1 R53.1 R54.1 R55.1 R56.1 R57.1 R63.2 S2.1 SB1.2 U3.8 U18.3 U18.21 U18.22 U25.11 U25.22 U25.28 U25.50 U25.75 U25.100 U26.4 VR1.2 | length 18793.7
  Top Layer w10: U3.8@1051.36,1713 1051.36,1745.36 1069,1763 1219,1763 1229.63,1752.37 C12.2@1229.63,1718 1229.63,1563.31 R13.2@1229.32,1563 ; v1(2600,2352) 2601,2351 C26.2@2641,2351 2641,2299 2679.76,2260.24 U25.75@2702.78,2260.24 ; C20.2@2884,1548 2884,1588 2899.63,1603.63 U25.11@2899.63,1665.76 ; U25.22@3116.17,1665.76 3116.17,1620.97 3126.13,1611 3402,1611 3417,1596 C24.2@3417,1571 ; U25.28@3236.24,1766.15 3398.85,1766.15 3416,1749 3416,1656.32 3460,1612.32 3460,1507 3443,1490 3419,1490 C25.2@3417,1492 ; C14.2@3574,2433.63 3574.63,2433 U18.3@3688.21,2433
  Top Layer w12: R14.1@175.69,1103 175.69,1130.69 198,1153 v1(351,1153) ; R15.1@437.93,1103 437.93,1153.93 v1(439,1155) ; R16.1@700.17,1103 700.17,1151.17 v1(701,1152) ; v1(962,1153) 962.42,1152.58 R17.1@962.42,1103 ; R18.1@1224.66,1103 1224.66,1151.66 v1(1225,1152) ; R19.1@1486.91,1103 1486.91,1152.91 v1(1487,1153) ; v1(1749,1154) 1749.15,1153.85 R20.1@1749.15,1103 ; v1(2011,1153) 2011.39,1152.61 R21.1@2011.39,1103 ; v1(2273,1153) 2273.64,1152.36 R22.1@2273.64,1103 ; R23.1@2535.88,1103 2535.88,1151.88 v3(2536,1152) ; C17.2@2564,1577.37 2626.37,1577.37 2642,1593 2642,1726.54 U25.100@2641.76,1726.78 ; R24.1@2798.13,1103 2798.13,1151.13 v1(2799,1152) ; R25.1@3060.37,1103 3060.37,1150.37 v1(3061,1151) ; v1(3214,2460) 3214,2388.32 C19.2@3213.69,2388 3213.69,2265.32 3236.24,2242.76 U25.50@3236.24,2199.22 ; R52.1@3453.69,1103 3453.69,1152.69 v1(3454,1153) ; R53.1@3698.37,1103 3698.37,1152.37 v1(3699,1153) ; R54.1@3913.69,1103 3913.69,1153.69 v1(3915,1155) ; P18.13@3929,3253 3929,3309 3950,3330 4570,3330 4590,3310 4590,3000 4575,2985 SB1.2@4575,2965 ; v1(4002,2115) 4060,2115 4075,2130 4075,2192.63 R63.2@4074.63,2193 ; R55.1@4158.37,1103 4158.37,1152.37 v1(4160,1154) ; v1(4383,1154) 4383.37,1153.63 R56.1@4383.37,1108 ; R57.1@4608.37,1103 4608.37,1149.37 v1(4611,1152)
  Top Layer w20: v3(1072,1858) 1117,1813 1241,1813 1275,1779 1275,1726 1264,1715 1232.63,1715 C12.2@1229.63,1718 ; v1(1906,1300) 1907.8,1298.2 U26.4@2041.83,1298.2 ; v1(1907,1654) 1907,1676 S2.1@1969,1738 ; v3(2413,1578) 2563.37,1578 C17.2@2564,1577.37 ; v3(2536,1152) 2538,1154 v3(2538,1424) ; C20.2@2884,1548 2885,1547 v3(2885,1424) ; v3(3390,1392) 3417,1419 C25.2@3417,1492 C24.2@3417,1571 ; 3892,2425 3894,2423 3917,2423 3926.69,2432.68 C15.2@3974,2432.68 3975.31,2434 v3(4024,2434)
  Top Layer w30: v3(1935,1934) 1939,1938 D34.A@1989,1938 ; v1(3450,2433) 3573.37,2433 C14.2@3574,2433.63
  Top Layer w40: C6.2@656,2499.63 962.37,2499.63 1008,2454 1008,1922 v3(1072,1858)
  Bottom Layer w10: 3060,2352 3061,2353
  Bottom Layer w12: v1(351,1153) 701,1153 v1(962,1153) 1094,1153 v1(1487,1153) 1905,1153 v1(2011,1153) v1(2273,1153) 3061,1153 v1(3061,1151) ; 3390,1153 v1(3454,1153) v1(3699,1153) 4000,1153 ; 4002,1155 4000,1153 ; v1@4605,1153 4000,1153
  Bottom Layer w20: 1905,1153 1905,1904 v3(1935,1934) 2054,1934 2120,2000 P21.1@2120,2310 ; v3(2413,1578) 2413,1465 2454,1424 v3(2538,1424) v3(2885,1424) ; v1(2600,2352) 3060,2352 ; v1@3061,1153 3061,2353 3061,2397 3124,2460 v1(3214,2460) ; 3390,1153 v3(3390,1392) ; v1(3450,2433) 3423,2460 v1(3214,2460) ; 4002,1155 v1(4002,2115) 4002,2412 v3(4024,2434) ; v1(3214,2460) 3214,2834 3285,2905 3781,2905 3873,2997 3874,2997 3880,3003 3880,3204 ; 3880,3204 3880,3219 3914,3253 P18.13@3929,3253 3880,3204
  Bottom Layer w40: v3(1072,1858) 1094,1836 1094,1153
+5V: C2.1 C4.2 C28.2 C29.2 L1.2 P16.1 P18.15 R3.1 R68.1 R77.1 VR1.3 | length 9266
  Top Layer w30: P16.1@9,2948 142,2948 180,2910 C29.2@270,2910 273,2913 R68.1@384,2913 v3(384,2846) ; v4(150,2367) 150,2227 215,2162 390,2162 416.55,2188.55 VR1.3@416.55,2250.89 ; v3(1132,2949) 1132,2946 1186,2892 v3(1186,2181) ; v6(3555,3130) C28.2@3555,3189.92 3704.92,3189.92 3768,3253 P18.15@3829,3253 3829,3334 3865,3370 4590,3370 4635.31,3324.69 R77.1@4635.31,2830
  Top Layer w40: v4(646,1809) 891,1809 935,1853 934,1854 v3(934,2178) 934,2181 v3@936,2183
  Bottom Layer w20: P18.15@3827,3255 P18.15@3829,3253
  Bottom Layer w30: P16.1@9,2948 P16.1@22,2935 ; v3(1186,2181) 1191,2176 1941,2176 2005,2240 2005,2380 2117,2492 2948,2492 3036,2580 3036,2864 3159,2987 3487,2987 3555,3055 v6(3555,3130)
  Bottom Layer w40: v4(150,2367) 583,2367 646,2304 v4(646,1809) ; v3(934,2178) v3@1180,2178
  Bottom Layer w50: 385,2935 399,2949 v3(1132,2949)
  other v3: 645,1748
+24V: C1.2 C13.2 D1.2 P4.1 P5.1 P6.1 P8.1 P8.2 R1.2 R26.1 R27.1 R28.1 R29.1 R30.1 R31.1 R32.1 R33.1 R34.1 R35.1 R36.1 R37.1 R38.2 R39.2 R40.2 R41.2 R42.2 R43.2 R44.2 R45.2 R46.1 R47.1 R48.1 R49.1 R50.1 R51.1 U1.5 U16.10 | length 13310.7
  Top Layer w12: R38.2@1325.63,3014 1325.63,3060.63 v1(1327,3062) ; v1(1526,3062) 1547.77,3040.23 R39.2@1547.77,3014 ; R40.2@1769.92,3014 1769.92,3061.92 v1(1771,3063) ; v1(1992,3061) 1992.06,3060.94 R41.2@1992.06,3014 ; v1(2214,3060) 2214.2,3059.8 R42.2@2214.2,3014 ; R43.2@2436.34,3014 2436.34,3061.34 v1(2437,3062) ; R44.2@2658.49,3014 2658.49,3061.49 v1(2660,3063) ; v1(2880,3062) 2880,3014.63 R45.2@2880.63,3014
  Top Layer w20: R26.1@293.32,523.62 293.32,413.68 v1(294,413) ; v1(554,413) 555.6,414.6 R27.1@555.6,523.62 ; R28.1@817.87,523.62 817.87,414.13 v1(819,413) ; R29.1@1080.14,523.62 1080.14,414.14 1094.28,400 v1(1120,400) ; R30.1@1342.41,523.62 1342.41,414.59 v1(1344,413) ; v1(1604,413) 1604.69,413.69 R31.1@1604.69,523.62 ; R32.1@1866.96,523.62 1866.96,415.04 1877,405 v1(1900,405) ; R33.1@2129.23,523.62 2129.23,413.23 2152.46,390 v1(2170,390) ; v1(2391,414) 2391.5,414.5 R34.1@2391.5,523.62 ; v1(2653,414) 2653.78,414.78 R35.1@2653.78,523.62 ; R36.1@2916.05,523.62 2916.05,414.05 2940.1,390 v1(2975,390) ; R37.1@3178.32,523.62 3178.32,413.32 3201.65,390 v1(3225,390) ; v1(3553,413) 3554.05,414.05 R46.1@3554.05,523.62 ; R47.1@3789.77,528 3789.77,414.23 v1(3790,414) ; v1(4025,414) 4025.49,414.49 R48.1@4025.49,528 ; R49.1@4261.21,523.62 4261.21,414.79 v1(4262,414) ; v1(4496,413) 4496.94,413.94 R50.1@4496.94,523.62 ; R51.1@4732.66,523.62 4732.66,419.34 4734,418 v1(4734,413)
  Top Layer w30: v3(1770,2283) 1770,2285 1770.34,2285.34 C13.2@1770.34,2348
  Bottom Layer w12: v1(1327,3062) v1(1526,3062) v1@1992,3062 ; v1@1998,3062 v1(2437,3062) v1(2880,3062)
  Bottom Layer w20: 316,413 v1(554,413) v1(819,413) 997,413 1010,400 ; P4.1@998,154 1025,181 1025,385 1010,400 ; v1(4734,413) v1(4496,413) v1(3553,413) 3530,390 v1(3225,390) 3103,390 3080,413 3057,390 v1(2975,390) v1(2170,390) 2062,390 2039,413 2031,405 v1(1900,405) 1612,405 v1(1604,413) v1(1344,413) 1331,400 v1(1120,400) 1010,400
  Bottom Layer w30: 1757,2533 1770,2520 v3(1770,2283)
  Bottom Layer w50: v3(114,1909) 235,1909 316,1828 316,1658 ; 316,393 316,413 292,437 292,1634 316,1658 ; 395,1658 316,1658
  Bottom Layer w80: 395,1658 755,1658 ; 902,2432 1048,2578 1857,2578 1998,2719 v1@1998,3061 ; v1@1998,3062 P8.2@1998,3284 P8.1@2148,3284
  other v3: -39,1902
ADC12_IN14: U25.15
ADC12_IN15: U25.16
BLUE: R70.2 U25.85 | length 2623.2
  Top Layer w10: R70.2@889.32,2803 1109,2803 1132,2780 1132,2000 1219,1913 1753,1913 1862.06,2022.06 U25.85@2641.76,2022.06
Blue_LED: P20.1 Q3.3 | length 282.8
  Top Layer w10: P20.1@849,3283 849,3056 864,3041 Q3.3@864,3006.43
BOOT0: R71.1 S2.2 U25.94 | length 694.5
  Top Layer w10: R71.1@2094,1618 2094,1708 2124,1738 S2.2@2278,1738 2384.89,1844.89 U25.94@2641.76,1844.89
BOOT1: R76.1 U25.37 | length 150.7
  Top Layer w10: U25.37@3236.24,1943.32 3319,1943.32 3339,1963.32 R76.1@3339,2003
DCin: D1.1 P10.1
Dir1: U18.17 U22.11 | length 935.3
  Top Layer w10: U18.17@3889,2334.57 4232.43,2334.57 4274,2293 4484,2293 4514,2323 4514,2503 4534,2523 U22.11@4606.36,2523
DIR1+: R60.1 U22.10 | length 513.1
  Top Layer w10: U22.10@4606.36,2473 4889,2473 4938.37,2522.37 4938.37,2683
Dir2: U18.27 U22.13 | length 950.7
  Top Layer w10: U18.27@3818.13,2503.87 3818.13,2533 3828.13,2543 4174,2543 4370,2739 4456,2739 4572,2623 U22.13@4606.36,2623
DIR2+: R62.1 U22.12 | length 854.4
  Top Layer w10: U22.12@4606.36,2573 v2(4724,2573) ; v2(4724,2258) 4864,2258 4928.69,2193.31 R62.1@4928.69,2003
  Bottom Layer w10: v2(4724,2258) v2(4724,2573)
Dir3: U18.20 U22.1 | length 628.4
  Top Layer w10: U18.20@3889,2393.63 4084.63,2393.63 4364,2673 U22.1@4401.64,2673
DIR3+: R65.1 U22.2 | length 1995
  Top Layer w10: U22.2@4401.64,2623 v2(4489,2623) ; R65.1@4928.69,1313 4929,1313.31 v2(4929,1378)
  Bottom Layer w10: v2(4489,2623) 4394,2623 4359,2588 4359,2213 4399,2173 4779,2173 4819,2133 4819,1438 4879,1378 v2(4929,1378)
GND: C1.1 C4.1 C5.2 C6.1 C7.2 C8.1 C9.1 C10.2 C11.2 C12.1 C13.1 C14.1 C15.1 C16.2 C17.1 C18.1 C19.1 C20.1 C21.1 C22.1 C23.1 C24.1 C25.1 C26.1 C27.1 C28.1 C29.1 D2.1 D3.K D32.K P4.2 P5.2 P6.2 P6.3 P10.2 P12.1 P12.3 P15.1 P15.3 P16.2 P17.1 P17.3 P18.16 P19.1 P19.2 P21.4 Q1.2 Q2.2 Q3.2 R2.2 R4.2 R6.2 R71.2 R73.1 R74.1 R75.1 R76.2 S1.2 U1.2 U2.7 U2.18 U2.21 U2.25 U2.26 U3.1 U3.2 U3.3 U3.4 U3.7 U4.3 U5.3 U6.3 U7.3 U8.3 U9.3 U10.3 U11.3 U12.3 U13.3 U14.3 U15.3 U16.9 U17.3 U18.0 U18.4 U18.6 U18.23 U18.25 U19.3 U20.3 U21.3 U22.7 U23.3 U24.3 U25.10 U25.19 U25.20 U25.27 U25.49 U25.74 U25.99 U26.1 USB_TypeB1.4 VR1.1 | length 6388.4
  Top Layer w10: R2.2@91,2069.63 150.37,2069.63 v1(151,2069) ; v1(556,2616) 559.63,2619.63 R73.1@559.63,2693 ; v1(724,2633) R74.1@724,2693 ; U3.4@846.64,1563 U3.3@846.64,1613 U3.2@846.64,1663 ; U3.1@846.64,1713 U3.2@846.64,1663 ; R75.1@889,2693 987,2693 v1(988,2692) ; C12.1@1169,1718 1114,1663 U3.7@1051.36,1663 U3.2@846.64,1663 ; U16.9@1659,1989.73 1721.27,1989.73 v1(1722,1989) ; C13.1@1887.66,2348 1932,2348 1940,2340 v5(1940,2300) ; C17.1@2564,1638 2564,1733 2577.46,1746.46 U25.99@2641.76,1746.46 3057.11,1746.46 ; v1(2702,2390) 2701.63,2389.63 C26.1@2701.63,2351 2722.46,2330.17 U25.74@2722.46,2260.24 ; C21.1@2823.37,1473 2826,1475.63 2826,1581 2837,1592 2856,1592 2879.94,1615.94 U25.10@2879.94,1665.76 ; U25.19@3057.11,1665.76 3057.11,1746.46 ; U25.49@3236.24,2179.54 3156.54,2179.54 3135,2158 3135,2021 3143,2013 3143,1792 3112,1761 3071,1761 3057.11,1747.11 3057.76,1746.46 ; C27.1@3353.69,1718 3325.22,1746.46 U25.27@3236.24,1746.46 3076.8,1746.46 ; C24.1@3356.37,1571 3099,1571 3076.8,1593.2 U25.20@3076.8,1665.76 3076.8,1746.46 ; v1(3399,1960) 3399.63,1960.63 R76.2@3399.63,2003 ; C14.1@3574,2373 3604,2373 3644.31,2413.31 U18.4@3688.21,2413.31 ; U18.6@3688.21,2373.94 3759.08,2373.94 U18.0@3788.61,2403.47 U18.0@3837.82,2452.68 ; U18.25@3857.5,2503.87 3857.5,2472.37 U18.0@3837.82,2452.68 ; 3937,2477 3937,2476 3913.69,2452.68 U18.23@3889,2452.68 U18.0@3837.82,2452.68 ; C16.2@4634,2748 4658,2748 4666,2740 4666,2706 v1(4665,2705) ; 3057.11,1746.46 3057.76,1746.46 ; 3057.76,1746.46 3076.8,1746.46
  Top Layer w12: U2.7@3941.17,1594.3 4042.8,1594.3 v1(4044,1595.5) ; U2.21@4212.83,1568.7 4128,1568.7 ; U2.25@4212.83,1671.07 U2.26@4212.83,1696.66 4151.16,1696.66 4128,1673.5 4128,1568.7 ; C9.1@4457,1746.5 C8.1@4457,1826.5 ; C10.2@4462.31,1401.5 4462.31,1441.5 ; C11.2@4462.31,1481.5 4462.31,1441.5 ; C7.2@5002,310.53 5002,225.22 R6.2@5002.68,224.53 R6.2@5002.68,218.47 ; 4128,1568.7 4128,1509.5 4145.57,1491.93 U2.18@4212.83,1491.93 4301.57,1491.93 4352,1441.5 4462.31,1441.5
  Bottom Layer w10: P21.4@2420,2310 2500,2390 v1(2702,2390) ; v1(3399,1960) 3399,1933 3359,1893 3200,1893 3151,1942 v1(3141,1942) 3141,2277 3175,2311 3177,2309 v1(3269,2309) 3445,2309 v1(3446,2310)
  Bottom Layer w12: v1(4044,1595.5) v1(4129,1595.5)
  other v1: 1666,1641 4294,2342 4109,2495 4164,2606
GREEN: R69.2 U25.86 | length 2784.2
  Top Layer w10: R69.2@724.47,2803 749,2803 774,2778 774,2633 789,2618 1059,2618 1099,2578 1099,1978 1194,1883 1758,1883 1877.37,2002.37 U25.86@2641.76,2002.37
Green_LED: P20.2 Q2.3 | length 277.1
  Top Layer w10: Q2.3@697.8,3006.43 697.8,3281.8 P20.2@699,3283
